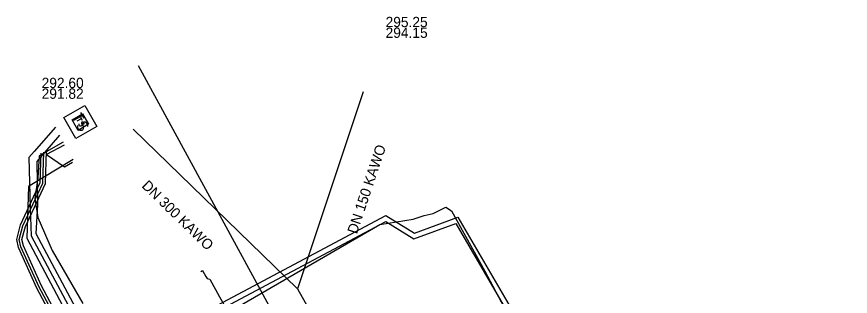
# Model space of a CAD drawing. Extents: x -600391 to -599491, y -1160176 to -1159402.
# Drawn here: x -600118 to -600053.1, y -1159721.6 to -1159699.8 of the extents above; entities that cross this region are included whole.
import ezdxf

# ---------------------------------------------------------------- set-up
doc = ezdxf.new("R2010")
doc.units = 0
for name, color, linetype in [('25', 7, 'Continuous'), ('Vrstva 12', 7, 'Continuous'), ('Vrstva 13', 7, 'Continuous'), ('Vrstva 19', 7, 'Continuous'), ('Vrstva 42', 7, 'Continuous'), ('Vrstva 43', 7, 'Continuous'), ('Vrstva 44', 7, 'Continuous'), ('Vrstva 45', 7, 'Continuous'), ('Vrstva 55', 7, 'Continuous'), ('Vrstva 9', 7, 'Continuous')]:
    doc.layers.add(name, color=color, linetype=linetype)

# ---------------------------------------------------------------- blocks, each defined once
blk = doc.blocks.new('NN640')
at = {"layer": '25'}
for points in [[(-1.89, 1.89), (1.89, 1.89)], [(-1.89, -1.89), (-1.89, 1.89)], [(1.89, 1.89), (1.89, -1.89)], [(-1.26, 0.79), (-0.22, 0.79)], [(-0.73, 0.79), (-0.73, -0.79)], [(1.2, 0.66), (0.94, 0.79), (0.66, 0.79), (0.41, 0.66), (0.28, 0.47), (0.28, 0.41), (0.41, 0.22), (1.13, -0.16), (1.26, -0.32), (1.26, -0.47), (1.13, -0.66), (0.91, -0.79), (0.63, -0.79), (0.5, -0.73), (0.28, -0.6)], [(1.89, -1.89), (-1.89, -1.89)]]:
    blk.add_lwpolyline(points, dxfattribs=at)
blk = doc.blocks.new('VN640')
at = {"layer": '25'}
for points in [[(-1.89, 1.89), (1.89, 1.89)], [(-1.89, -1.89), (-1.89, 1.89)], [(-1.26, 0.79), (-0.22, 0.79)], [(-0.73, 0.79), (-0.73, -0.79)], [(1.2, 0.66), (0.94, 0.79), (0.66, 0.79), (0.41, 0.66), (0.28, 0.47), (0.28, 0.41), (0.41, 0.22), (1.13, -0.16), (1.26, -0.32), (1.26, -0.47), (1.13, -0.66), (0.91, -0.79), (0.63, -0.79), (0.5, -0.73), (0.28, -0.6)], [(1.89, 1.89), (1.89, -1.89)], [(1.89, -1.89), (-1.89, -1.89)]]:
    blk.add_lwpolyline(points, dxfattribs=at)

msp = doc.modelspace()

# ---------------------------------------------------------------- linework, layer by layer
at = {"layer": 'Vrstva 13'}
msp.add_lwpolyline([(-600096.52, -1159725.62), (-600096.906, -1159724.909), (-600108.499, -1159703.648)], dxfattribs=at)
at = {"layer": 'Vrstva 19'}
for points in [[(-600103.659, -1159719.626), (-600103.529, -1159719.551), (-600103.27, -1159720)], [(-600103.27, -1159720), (-600103.16, -1159720.17), (-600102.96, -1159720.23)], [(-600102.96, -1159720.23), (-600102.19, -1159721.6), (-600101.61, -1159722.63), (-600101.02, -1159723.68), (-600092.94, -1159739.82), (-600092.8, -1159740.06), (-600092.67, -1159740.29), (-600076.86, -1159768.54), (-600076.76, -1159768.72), (-600076.64, -1159768.93), (-600071.93, -1159777.29), (-600071.77, -1159777.6), (-600071.68, -1159777.76), (-600070.82, -1159779.35), (-600070.74, -1159779.5)]]:
    msp.add_lwpolyline(points, dxfattribs=at)
at = {"layer": 'Vrstva 42'}
for points in [[(-600114.347, -1159709.587), (-600116.223, -1159710.643), (-600116.34, -1159712.35), (-600116.57, -1159713.96), (-600116.33, -1159715.44), (-600115.21, -1159717.98), (-600112.84, -1159722.12)], [(-600112.14, -1159728.97), (-600112.77, -1159727.87), (-600112.94, -1159726.99), (-600116.22, -1159720.83), (-600117.64, -1159717.7), (-600117.77, -1159717.14), (-600117.49, -1159716.07), (-600115.94, -1159712.75), (-600115.87, -1159710.34)], [(-600111.966, -1159728.871), (-600112.58, -1159727.799), (-600112.749, -1159726.923), (-600116.04, -1159720.742), (-600117.45, -1159717.635), (-600117.564, -1159717.143), (-600117.301, -1159716.138), (-600115.741, -1159712.797), (-600115.667, -1159710.243)], [(-600114.285, -1159709.799), (-600115.65, -1159710.537), (-600114.25, -1159711.49), (-600113.63, -1159711.13)], [(-600112.314, -1159729.069), (-600112.96, -1159727.941), (-600113.131, -1159727.057), (-600116.4, -1159720.918), (-600117.83, -1159717.765), (-600117.976, -1159717.137), (-600117.679, -1159716.002), (-600116.139, -1159712.703), (-600116.073, -1159710.442)], [(-600113.587, -1159710.924), (-600117.062, -1159713.011), (-600117.198, -1159717.038), (-600113.7, -1159723.598), (-600112.966, -1159725.104), (-600111.784, -1159730.443), (-600107.117, -1159738.748), (-600102.76, -1159745.888), (-600101.28, -1159746.694), (-600099.146, -1159748.032), (-600092.5, -1159744.254), (-600090.695, -1159745.234), (-600084.1, -1159756.935), (-600076.609, -1159770.241), (-600073.727, -1159776.069), (-600071.793, -1159774.992), (-600066.101, -1159771.804), (-600065.234, -1159771.631), (-600061.629, -1159769.471), (-600058.545, -1159767.99), (-600043.165, -1159759.259)]]:
    msp.add_lwpolyline(points, dxfattribs=at)
at = {"layer": 'Vrstva 44'}
for points in [[(-600114.966, -1159708.406), (-600116.612, -1159710.288), (-600117.032, -1159710.768), (-600116.928, -1159714.67), (-600116.844, -1159716.851), (-600113.344, -1159723.416), (-600112.98, -1159724.039), (-600110.819, -1159725.663), (-600108.608, -1159726.025), (-600089.262, -1159715.74), (-600087.066, -1159717.097), (-600083.821, -1159715.904), (-600075.369, -1159730.4), (-600075.529, -1159731.46), (-600082.814, -1159736.532), (-600077.792, -1159746.906), (-600074.831, -1159751.872), (-600065.208, -1159769.174), (-600065.108, -1159769.356), (-600064.918, -1159769.684)], [(-600114.638, -1159709.021), (-600116.268, -1159710.917), (-600116.4, -1159711.071), (-600116.356, -1159714.441), (-600116.49, -1159716.664), (-600112.995, -1159723.221), (-600112.675, -1159723.767), (-600110.657, -1159725.284), (-600108.677, -1159725.608), (-600089.247, -1159715.279), (-600087.021, -1159716.654), (-600083.644, -1159715.413), (-600074.952, -1159730.32), (-600075.159, -1159731.69), (-600082.305, -1159736.665), (-600077.44, -1159746.716), (-600074.484, -1159751.672), (-600065.377, -1159768.02), (-600064.876, -1159768.949), (-600064.038, -1159769.975), (-600062.17, -1159770.335), (-600061.218, -1159769.79)]]:
    msp.add_lwpolyline(points, dxfattribs=at)
at = {"layer": 'Vrstva 55'}
msp.add_lwpolyline([(-600100.77, -1159722.37), (-600089.72, -1159715.98), (-600087.12, -1159715.56), (-600086.28, -1159715.27), (-600085.57, -1159715.11), (-600084.58, -1159714.63), (-600084.15, -1159714.9), (-600081.55, -1159719.6), (-600078.38, -1159725.54)], dxfattribs=at)
at = {"layer": 'Vrstva 9'}
for p in [(-600091.01, -1159705.66), (-600108.908, -1159708.57)]:
    msp.add_line(p, (-600096.14, -1159720.98), dxfattribs=at)
msp.add_lwpolyline([(-600096.14, -1159720.98), (-600088.165, -1159735.142), (-600087.296, -1159736.685), (-600087.045, -1159737.13), (-600086.216, -1159738.602), (-600079.318, -1159750.843)], dxfattribs=at)

# ---------------------------------------------------------------- block references
at = {"layer": 'Vrstva 43', "xscale": 0.5, "yscale": 0.5, "rotation": -59.99999999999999}
msp.add_blockref('NN640', (-600113.026, -1159708.011), dxfattribs=at)
at = {"layer": 'Vrstva 45', "xscale": 0.25, "yscale": 0.25, "rotation": -59.99999999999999}
msp.add_blockref('VN640', (-600113.026, -1159708.011), dxfattribs=at)

# ---------------------------------------------------------------- texts
at = {"layer": 'Vrstva 12'}
for s, p in [('295.25', (-600089.276, -1159700.639)), ('294.15', (-600089.276, -1159701.471)), ('292.60', (-600116.034, -1159705.374)), ('291.82', (-600116.034, -1159706.206))]:
    msp.add_text(s, height=0.8, dxfattribs=at).set_placement(p)
for s, rotation, p in [('DN 150 KAWO', 71.48655, (-600091.514, -1159716.761)), ('DN 300 KAWO', 315.81462, (-600108.298, -1159713.032))]:
    msp.add_text(s, height=0.8, rotation=rotation, dxfattribs=at).set_placement(p)

doc.saveas('drawing.dxf')
